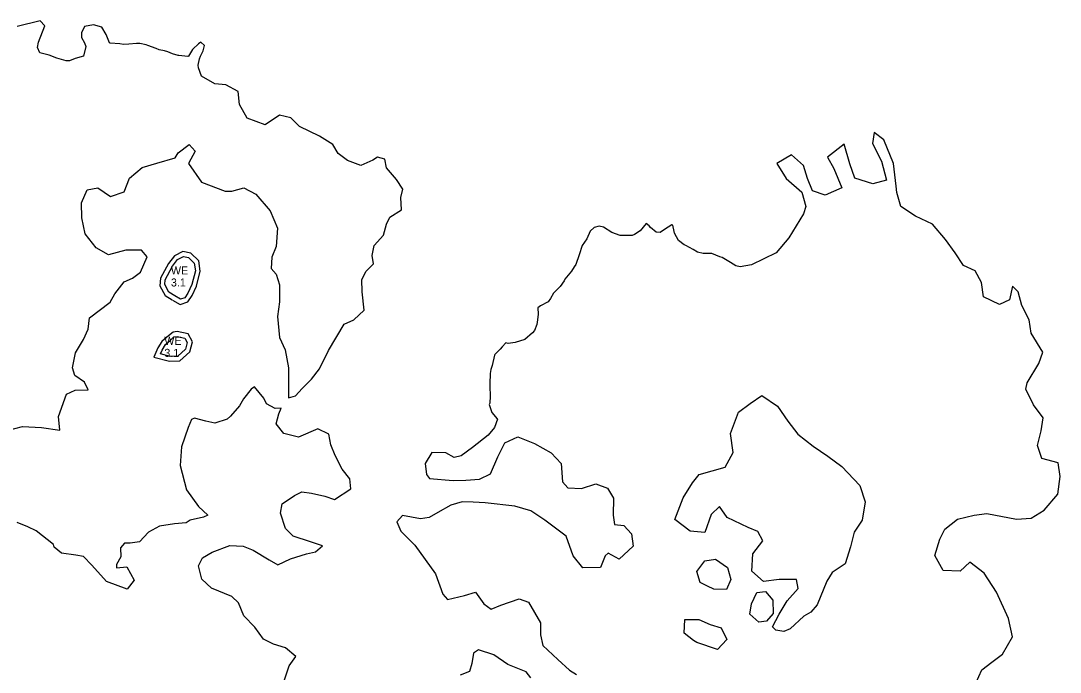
# Model space of a CAD drawing. Extents: x 2160437 to 2172832, y 205694 to 212444.
# Drawn here: x 2165786 to 2166435, y 209555 to 209962 of the extents above; entities that cross this region are included whole.
import ezdxf

# ---------------------------------------------------------------- set-up
doc = ezdxf.new("R2010")
doc.units = 0
for name, color, linetype in [('RD_EX_H2O_Pond', 7, 'Continuous'), ('RD_EX_H2O_txCode', 7, 'Continuous'), ('RD_EX_VEG_ShrubLine', 7, 'Continuous'), ('RD_EX_VEG_TreeLine', 7, 'Continuous')]:
    doc.layers.add(name, color=color, linetype=linetype)

msp = doc.modelspace()

# ---------------------------------------------------------------- linework, layer by layer
at = {"layer": 'RD_EX_H2O_Pond'}
for points in [[(2165882.25, 209790.27), (2165878.63, 209792.65), (2165876.08, 209797.33), (2165876.27, 209800.42), (2165880.9, 209808.9), (2165884.06, 209812.95), (2165887.77, 209814.94), (2165890.77, 209814.24), (2165894.4, 209810.76), (2165895.18, 209805.96), (2165892.93, 209797.42), (2165890.5, 209791.96), (2165888.46, 209789.1), (2165885.95, 209788.17)], [(2165881.63, 209764.65), (2165883.77, 209764.97), (2165888.59, 209763.96), (2165890.09, 209761.21), (2165889.04, 209757), (2165884.22, 209752.69), (2165879.3, 209752.47), (2165873.34, 209754.07), (2165874.39, 209756.42), (2165876.54, 209759.83), (2165879.39, 209762.37)]]:
    msp.add_lwpolyline(points, close=True, dxfattribs=at)
at = {"layer": 'RD_EX_VEG_ShrubLine'}
for points in [[(2165777.51, 209706.18), (2165787.06, 209708.65), (2165799.06, 209708.05), (2165810.55, 209706.3), (2165809.64, 209714.88), (2165814.54, 209728.78), (2165820.12, 209731.3), (2165828.13, 209731.56), (2165825.83, 209736.39), (2165819.8, 209740.62), (2165818.36, 209745.35), (2165820.2, 209754.8), (2165825.33, 209763.06), (2165828.23, 209769.58), (2165828.95, 209776.53), (2165841.92, 209786.3), (2165844.77, 209791.67), (2165850.6, 209799.07), (2165855.84, 209801.46), (2165860.92, 209805.11), (2165865.06, 209814.63), (2165861.59, 209818.89), (2165851.67, 209818.85), (2165840.81, 209815.87), (2165833.09, 209820.39), (2165826.31, 209829.03), (2165824.17, 209839.16), (2165824.05, 209848.48), (2165827.47, 209856.59), (2165834.18, 209857.79), (2165842.23, 209852.39), (2165850.64, 209855.38), (2165854.08, 209863.93), (2165861.89, 209870.46), (2165871.16, 209873.33), (2165882.5, 209876.56), (2165884.47, 209879.77), (2165891.34, 209884.99), (2165894.95, 209880.65), (2165890.95, 209873.08), (2165898.91, 209861.36), (2165913.7, 209855.79), (2165917.86, 209855.75), (2165925.46, 209857.92), (2165932.89, 209853.8), (2165941.83, 209843.46), (2165946.41, 209832.71), (2165945.67, 209821.22), (2165942.93, 209814.45), (2165942.46, 209807.48), (2165945.68, 209803.87), (2165947.65, 209797.27), (2165947.61, 209786.56), (2165946.43, 209777.36), (2165947.73, 209764.34), (2165951.13, 209756.65), (2165953.35, 209745.31), (2165953.34, 209726.69), (2165957.6, 209727.88), (2165961.86, 209732.35), (2165967.76, 209738.27), (2165972.71, 209744.7), (2165978.39, 209756.26), (2165988.13, 209772.64), (2165994.17, 209775.41), (2166000.63, 209781.35), (2165999.33, 209792.74), (2165999.05, 209800.49), (2166001.78, 209805.82), (2166006.34, 209810.34), (2166005.5, 209815.62), (2166006.89, 209821.81), (2166012.63, 209828.17), (2166014.58, 209835.02), (2166016.6, 209839.57), (2166023.87, 209844.06), (2166023.45, 209851.7), (2166024.66, 209857.07), (2166020.67, 209863.02), (2166014.57, 209870.36), (2166013.4, 209875.7), (2166008.92, 209877.06), (2166006.07, 209875.15), (2165998.49, 209871.79), (2165990.1, 209874.98), (2165984.32, 209879.36), (2165981.02, 209884.82), (2165972.68, 209890.17), (2165960.21, 209896.25), (2165954.77, 209901.58), (2165947.75, 209903.16), (2165938.76, 209897.25), (2165927.57, 209901.31), (2165922.69, 209909.94), (2165921.88, 209917.93), (2165914.25, 209922.23), (2165907.27, 209922.88), (2165898.88, 209927.51), (2165898.88, 209927.51), (2165897.12, 209932.75), (2165896.97, 209934.45), (2165897.64, 209938.42), (2165898.34, 209940.2), (2165899.94, 209943.4), (2165900.76, 209946.67), (2165898.51, 209948.76), (2165897.03, 209947.87), (2165893.61, 209944.48), (2165893.33, 209944.25), (2165890.92, 209940.05), (2165890.44, 209939.8), (2165884.73, 209940.44), (2165884.35, 209940.61), (2165880.77, 209941.6), (2165878.04, 209942.82), (2165875.82, 209943.49), (2165872.52, 209944.05), (2165870.55, 209944.92), (2165865.42, 209946.66), (2165864.39, 209947.21), (2165860.52, 209948.11), (2165858.4, 209948.05), (2165853.48, 209947.6), (2165850.25, 209947.49), (2165847.86, 209947.83), (2165841.93, 209948.19), (2165841.59, 209948.44), (2165839.5, 209953.55), (2165839.5, 209953.55), (2165836.68, 209958.25), (2165831.45, 209959.76), (2165831.45, 209959.76), (2165825.99, 209958.73), (2165823.94, 209954.74), (2165824, 209951.8), (2165825.98, 209948.47), (2165826.78, 209946.21), (2165825.24, 209940.08), (2165825.24, 209940.08), (2165819.96, 209938.61), (2165816.57, 209937.12), (2165814.41, 209937.17), (2165808.64, 209938.92), (2165808.64, 209938.92), (2165808.64, 209938.92), (2165803.73, 209940.74), (2165798.84, 209942), (2165798.05, 209942.26), (2165796.49, 209945.5), (2165797.23, 209948.8), (2165801.12, 209959.07), (2165798.16, 209962.21), (2165783.89, 209958.64)], [(2166380.69, 209544.12), (2166386.41, 209556.56), (2166392.54, 209561.37), (2166399.35, 209566.35), (2166405.58, 209577.24), (2166402.96, 209588.75), (2166395.57, 209605.18), (2166387.89, 209616.93), (2166378.98, 209623.82), (2166372.93, 209618.38), (2166362.23, 209618.63), (2166357.09, 209628.04), (2166360.06, 209638.35), (2166363.29, 209644.47), (2166371.13, 209650.67), (2166381.56, 209653.3), (2166389.57, 209654.26), (2166408.15, 209650.7), (2166417.24, 209651.41), (2166425.37, 209656.39), (2166433.94, 209666.35), (2166435.35, 209677.49), (2166434.08, 209685.87), (2166423.82, 209688.69), (2166421.23, 209696.82), (2166423.42, 209705.93), (2166424.8, 209714.08), (2166418.69, 209722.12), (2166413.78, 209732.02), (2166414.7, 209735.93), (2166422, 209748.14), (2166424.56, 209755.16), (2166417.17, 209767.02), (2166415.95, 209775.25), (2166411.33, 209784.19), (2166409.11, 209792.87), (2166405.54, 209796.41), (2166403.68, 209787.75), (2166397.33, 209784.85), (2166387.42, 209789.79), (2166386.08, 209798.56), (2166382.25, 209806.05), (2166375.01, 209809.19), (2166369.64, 209817.26), (2166363.62, 209825.5), (2166355.48, 209835.17), (2166344.94, 209840.04), (2166335.71, 209846.24), (2166333.35, 209854.87), (2166332.89, 209858.92), (2166331.24, 209873.12), (2166325.15, 209887.88), (2166319.18, 209892.49), (2166318.09, 209885.54), (2166323.68, 209874.49), (2166326.76, 209862.65), (2166318.27, 209860.34), (2166307.05, 209863.96), (2166303.94, 209872.8), (2166300.31, 209885.01), (2166289.95, 209876.95), (2166293.91, 209870), (2166299.01, 209857.85), (2166288.61, 209853.16), (2166280.6, 209855.93), (2166277.49, 209863.69), (2166275.01, 209871.78), (2166267.43, 209878.44), (2166258.39, 209873.02), (2166264.11, 209863.59), (2166274.01, 209855.17), (2166276.44, 209846.15), (2166275, 209841.63), (2166265.85, 209826.65), (2166257.85, 209817.15), (2166242.56, 209809.62), (2166235.37, 209808.55), (2166232.7, 209809.1), (2166229.41, 209811.1), (2166224.25, 209814.22), (2166222.75, 209814.71), (2166217.75, 209816.75), (2166215.96, 209816.81), (2166212.43, 209816.84), (2166208.86, 209817.6), (2166206.07, 209819.3), (2166201.5, 209821.69), (2166200.52, 209822.13), (2166196.97, 209824.98), (2166194.42, 209829.48), (2166194.19, 209830.58), (2166193.3, 209834.52), (2166192.66, 209834.71), (2166188.26, 209831.76), (2166185.45, 209829.92), (2166183.02, 209830.18), (2166179.39, 209833.07), (2166178.68, 209834.11), (2166176.71, 209835.62), (2166172.91, 209830.95), (2166169.45, 209828.68), (2166168.06, 209828.02), (2166161.3, 209827.93), (2166160.41, 209827.97), (2166155.23, 209829.81), (2166150.02, 209833.22), (2166147.29, 209833.8), (2166144.34, 209833.11), (2166141.7, 209830.83), (2166139.61, 209825.95), (2166136.68, 209821.8), (2166134.83, 209815.99), (2166134.83, 209815.99), (2166132.79, 209809.99), (2166131.82, 209808.42), (2166130.16, 209805.71), (2166126, 209800.83), (2166125.45, 209799.8), (2166123.05, 209796.24), (2166118.93, 209792.08), (2166116.89, 209788.71), (2166115.6, 209786.65), (2166110.82, 209784.05), (2166109.09, 209782.82), (2166109.34, 209778.89), (2166108.8, 209775.23), (2166108.48, 209772.46), (2166106.95, 209768.6), (2166105.71, 209767.24), (2166100.84, 209763.04), (2166100.84, 209763.04), (2166094.83, 209761.17), (2166090.47, 209760.57), (2166089.08, 209760.91), (2166086.86, 209758.36), (2166085.51, 209756.96), (2166082.13, 209753.65), (2166081.93, 209753.19), (2166080.58, 209746.89), (2166079.73, 209744.36), (2166079.32, 209741.81), (2166079.02, 209735.41), (2166079.05, 209733.84), (2166079.26, 209727.57), (2166079.08, 209723.29), (2166078.6, 209722.42), (2166080.28, 209717.4), (2166083.65, 209713.54), (2166083.81, 209713.28), (2166082.01, 209708), (2166077.99, 209703.22), (2166068.26, 209695.65), (2166061.25, 209690.31), (2166056.88, 209689.26), (2166051.54, 209692.17), (2166042.84, 209692.41), (2166038.65, 209685.46), (2166039.41, 209678.58), (2166041.34, 209676.17), (2166056.19, 209674.84), (2166064.14, 209675.13), (2166072.66, 209675.7), (2166079.56, 209679.17), (2166084.17, 209689.75), (2166088.35, 209698.53), (2166096.51, 209702.17), (2166107.06, 209698.11), (2166117.33, 209692.19), (2166123.68, 209685.64), (2166124.47, 209674.11), (2166127.84, 209670.25), (2166136.25, 209669.97), (2166145.19, 209672.9), (2166152.49, 209670.11), (2166156.42, 209663.82), (2166156.04, 209653.36), (2166156.94, 209647.42), (2166162.76, 209646.82), (2166167.46, 209641.65), (2166168.63, 209633.86), (2166159.78, 209625.8), (2166153.02, 209629.62), (2166151.09, 209627.94), (2166148.27, 209620.56), (2166137.09, 209620.35), (2166131.21, 209627.96), (2166126.72, 209640.13), (2166113.4, 209650.23), (2166104.67, 209655.93), (2166094.61, 209658.86), (2166076.08, 209660.92), (2166068.59, 209661.43), (2166061.77, 209661.64), (2166054.77, 209659.57), (2166046.65, 209655.01), (2166041.19, 209651.71), (2166035.69, 209650.98), (2166024.44, 209653.07), (2166020.94, 209649.08), (2166023.39, 209643.36), (2166032.3, 209634.58), (2166045.12, 209616.62), (2166049.79, 209603.82), (2166052.54, 209600.6), (2166063.28, 209603.1), (2166070.1, 209605.15), (2166075.41, 209597.89), (2166079.99, 209594.49), (2166086.04, 209597.07), (2166097.35, 209601.04), (2166103.13, 209598.92), (2166110.71, 209585.92), (2166110.67, 209578.49), (2166112.27, 209571.87), (2166121.48, 209563.15), (2166128.85, 209556.42), (2166133.14, 209553.6)], [(2165950.44, 209549.08), (2165953.67, 209559.19), (2165957.97, 209565), (2165951.41, 209570.46), (2165943.84, 209572.65), (2165937.6, 209575.78), (2165932.21, 209583.27), (2165925.42, 209590.28), (2165922, 209598.52), (2165917.92, 209602.43), (2165905.27, 209607.69), (2165899.14, 209613.32), (2165897.09, 209621.59), (2165899.53, 209626.68), (2165905.73, 209630.2), (2165916.69, 209634.41), (2165924.97, 209633.82), (2165931.28, 209631.47), (2165941.33, 209625.46), (2165946.6, 209622.2), (2165954.65, 209625.99), (2165964.58, 209629.11), (2165970.1, 209630.29), (2165974.61, 209634.1), (2165966.95, 209636.51), (2165956.27, 209640.07), (2165951.41, 209644.87), (2165948.22, 209654.46), (2165949.37, 209660.31), (2165957.16, 209665.57), (2165961.63, 209667.86), (2165967.58, 209666.94), (2165975.95, 209665.12), (2165982.1, 209663.02), (2165992.28, 209669.77), (2165991.55, 209675.91), (2165986.92, 209682.05), (2165982.56, 209690.62), (2165979.66, 209697.18), (2165978.46, 209703.89), (2165971.69, 209707.26), (2165959.52, 209701.95), (2165950.38, 209704.29), (2165945.65, 209710.39), (2165947.19, 209716.52), (2165948.66, 209720.23), (2165945.07, 209719.92), (2165939.58, 209722.9), (2165937.94, 209726.36), (2165932.03, 209733.52), (2165930.02, 209732.06), (2165925.24, 209726), (2165922.73, 209721.58), (2165917, 209715.22), (2165914.93, 209713.23), (2165907.23, 209710.84), (2165901.72, 209711.93), (2165894.61, 209713.91), (2165892.75, 209713.01), (2165890.64, 209708.04), (2165886.57, 209696.04), (2165885.59, 209684.21), (2165889.58, 209669.08), (2165897.19, 209658.61), (2165902.97, 209653.23), (2165900.13, 209651.94), (2165891.93, 209650.05), (2165889.29, 209648.4), (2165882.04, 209647.81), (2165872.69, 209646.42), (2165865.77, 209642.69), (2165860.28, 209636.68), (2165854.49, 209635.71), (2165850.8, 209635.8), (2165848.3, 209632.83), (2165848.55, 209627.26), (2165845.91, 209622.35), (2165845.89, 209620.45), (2165852.26, 209620.89), (2165856.91, 209612.55), (2165852.56, 209607.04), (2165839.55, 209611.92), (2165830.43, 209622.06), (2165825.35, 209627.4), (2165820.56, 209628.26), (2165811.55, 209629.45), (2165806.95, 209633.22), (2165806.57, 209635.02), (2165795.78, 209643.45), (2165790.5, 209646.07), (2165783.8, 209648.78)], [(2166104.72, 209551.61), (2166101.73, 209555.3), (2166090.33, 209559.91), (2166081.66, 209565.95), (2166072.07, 209569.12), (2166068.89, 209567.08), (2166067.78, 209560.48), (2166066.41, 209555.55), (2166060.6, 209553.32)]]:
    msp.add_lwpolyline(points, dxfattribs=at)
for points in [[(2166255.58, 209583.52), (2166259.77, 209591.48), (2166264.83, 209599.78), (2166271.73, 209607.36), (2166270.57, 209613.05), (2166259.88, 209613.06), (2166249.97, 209611.87), (2166242.8, 209618.35), (2166243.34, 209629.16), (2166249.63, 209637.26), (2166246.46, 209643.01), (2166240.52, 209645.57), (2166227.33, 209651.75), (2166222.49, 209658.61), (2166217.25, 209653.65), (2166213.29, 209642.46), (2166204.28, 209643.27), (2166194.67, 209650.48), (2166199.76, 209664.17), (2166205.71, 209673.38), (2166209.76, 209678.64), (2166226.1, 209683.18), (2166230.98, 209692.4), (2166229.41, 209704.4), (2166234.32, 209717.69), (2166241.65, 209723.03), (2166249, 209728.14), (2166258.68, 209721.37), (2166265.19, 209712.07), (2166271.45, 209703.84), (2166281.12, 209696.49), (2166290.15, 209690.13), (2166298.99, 209683.63), (2166310.26, 209671.82), (2166313.61, 209661.67), (2166311.67, 209650.16), (2166306.69, 209642.56), (2166304.4, 209633.49), (2166301.06, 209622.86), (2166292.89, 209617.53), (2166289.48, 209612.1), (2166283.61, 209597.2), (2166279.48, 209592.57), (2166275.12, 209590.09), (2166266.67, 209582.25), (2166262.71, 209580.67), (2166257.63, 209581.39)], [(2166210.48, 209611.16), (2166208.44, 209618.09), (2166213.46, 209624.71), (2166219.94, 209625.76), (2166227.46, 209620.57), (2166229.58, 209613.01), (2166226.83, 209606.92), (2166219.08, 209607.04), (2166215.03, 209608.99)], [(2166242.45, 209597.84), (2166245.89, 209604.94), (2166251.31, 209605.5), (2166255.79, 209600.24), (2166256.08, 209591.82), (2166251.91, 209587.09), (2166247.03, 209586.41), (2166241.38, 209591.47)], [(2166200.48, 209579.62), (2166200.88, 209587.97), (2166209.66, 209587.98), (2166216.79, 209584.89), (2166223.54, 209582.81), (2166227.12, 209575.55), (2166221.2, 209569.33), (2166208.27, 209573.71), (2166206.31, 209574.95)]]:
    msp.add_lwpolyline(points, close=True, dxfattribs=at)
at = {"layer": 'RD_EX_VEG_TreeLine'}
msp.add_lwpolyline([(2165880.77, 209787.66), (2165885.69, 209784.87), (2165890.36, 209786.61), (2165893.12, 209790.47), (2165895.77, 209796.43), (2165898.24, 209805.81), (2165897.2, 209812.23), (2165892.25, 209816.97), (2165887.34, 209818.12), (2165882.09, 209815.29), (2165878.39, 209810.56), (2165873.32, 209801.27), (2165873.03, 209796.65), (2165876.36, 209790.55), (2165880.6, 209787.76)], dxfattribs=at)
msp.add_lwpolyline([(2165881.19, 209767.62), (2165877.32, 209764.55), (2165874.22, 209761.79), (2165871.73, 209757.84), (2165869.17, 209752.09), (2165878.97, 209749.45), (2165885.42, 209749.74), (2165891.73, 209755.37), (2165893.29, 209761.61), (2165890.56, 209766.62), (2165883.86, 209768.02)], close=True, dxfattribs=at)

# ---------------------------------------------------------------- texts
at = {"layer": 'RD_EX_H2O_txCode'}
for s, p in [('WE', (2165879.87, 209803.68)), ('3.1', (2165879.87, 209796.18)), ('WE', (2165875.77, 209759.71)), ('3.1', (2165875.77, 209752.21))]:
    msp.add_text(s, height=5, dxfattribs=at).set_placement(p)

doc.saveas('drawing.dxf')
